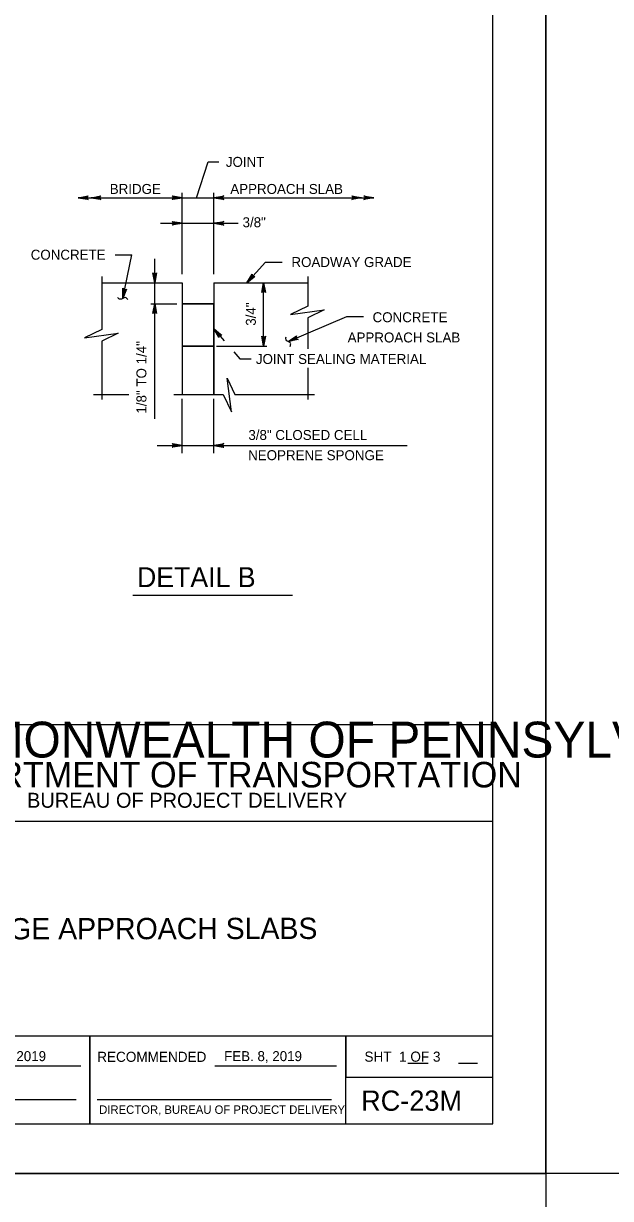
# Model space of a CAD drawing. Extents: x 638079 to 640019, y 297691 to 298879.
# Drawn here: x 638957.8 to 639134.4, y 298277.7 to 298631.2 of the extents above; entities that cross this region are included whole.
import ezdxf

# ---------------------------------------------------------------- set-up
doc = ezdxf.new("R2010")
doc.units = 0
doc.layers.add('1', color=7, linetype='Continuous')
doc.layers.add('PLT-BNDY', color=7, linetype='Continuous')

msp = doc.modelspace()

# ---------------------------------------------------------------- linework, layer by layer
at = {"layer": '1'}
for p, q in [((639009.91, 298578.75), (639013.4, 298589.57)), ((639013.4, 298589.57), (639016.61, 298589.57)), ((638974.31, 298578.75), (639063.24, 298578.75)), ((639005.54, 298555.74), (639005.54, 298580.25)), ((639015.08, 298555.74), (639015.08, 298580.25)), ((638999, 298571.05), (639022.46, 298571.05)), ((638985.41, 298561.59), (638990.41, 298561.59)), ((638987.7, 298548.47), (638990.41, 298561.59)), ((638997.32, 298512.27), (638997.32, 298560.41)), ((639025.06, 298553.2), (639030.61, 298559.39)), ((639030.61, 298559.39), (639035.62, 298559.39)), ((638981.39, 298555.01), (638981.39, 298539.15)), ((639043.36, 298555.01), (639043.36, 298546.18)), ((638981.39, 298553.2), (639005.54, 298553.2)), ((639005.54, 298553.2), (639005.54, 298519.53)), ((639005.54, 298553.2), (639005.54, 298546.86)), ((639015.08, 298553.2), (639015.08, 298546.86)), ((639015.08, 298553.2), (639043.36, 298553.2)), ((639030.05, 298534.15), (639030.05, 298553.2)), ((638996.14, 298546.86), (639003.95, 298546.86)), ((639005.54, 298546.86), (639005.54, 298534.15)), ((639005.54, 298546.86), (639015.08, 298546.86)), ((639015.08, 298546.86), (639015.08, 298519.53)), ((639037.49, 298535.48), (639055.14, 298543.04)), ((639043.36, 298542.66), (639043.36, 298533.34)), ((639055.14, 298543.04), (639060.14, 298543.04)), ((639015.08, 298539.31), (639018.19, 298535.72)), ((638981.39, 298535.63), (638981.39, 298518.07)), ((639005.54, 298534.15), (639015.08, 298534.15)), ((639015.92, 298534.15), (639031.05, 298534.15)), ((639021.13, 298532.35), (639022.95, 298530.26)), ((639022.95, 298530.26), (639026.35, 298530.26)), ((639043.36, 298527.58), (639043.36, 298518.07)), ((638978.87, 298519.53), (638989.49, 298519.53)), ((639003.06, 298519.53), (639017.92, 298519.53)), ((639021.44, 298519.53), (639045.41, 298519.53)), ((639005.54, 298501.96), (639005.54, 298518.27)), ((639015.08, 298501.96), (639015.08, 298518.27)), ((638998, 298504.24), (639073.25, 298504.24)), ((638990.71, 298459.2), (639038.76, 298459.2)), ((638938.35, 298317.61), (638975.04, 298317.61)), ((639015.35, 298317.61), (639052.04, 298317.61)), ((639073.45, 298318.41), (639079.6, 298318.41)), ((639088.71, 298318.41), (639094.45, 298318.41)), ((638901.43, 298307.53), (638973.67, 298307.53)), ((638979.96, 298307.53), (639050.52, 298307.53)), ((639115.03, 298285.23), (639115.03, 298285.23))]:
    msp.add_line(p, q, dxfattribs=at)
for points in [[(639099.03, 298300.23), (639099.03, 298864.23), (638313.03, 298864.23), (638313.03, 298300.23), (639099.03, 298300.23), (639099.03, 298326.59), (638899.03, 298326.59), (638899.03, 298391.26), (639099.03, 298391.26), (639099.03, 298420.23), (638899.03, 298420.23), (638899.03, 298300.23), (638977.83, 298300.23), (638977.83, 298326.59), (638977.83, 298300.23), (639054.83, 298300.23), (639054.83, 298326.59), (639054.83, 298314.27), (639099.03, 298314.27)], [(638974.31, 298578.75), (638977.29, 298579.31), (638977.06, 298579.15), (638976.94, 298578.95), (638976.91, 298578.75), (638976.94, 298578.55), (638977.06, 298578.35), (638977.29, 298578.19), (638974.31, 298578.75), (638977.06, 298578.35), (638976.94, 298578.55), (638974.31, 298578.75), (638976.91, 298578.75), (638976.94, 298578.95), (638974.31, 298578.75), (638977.06, 298579.15)], [(638978.14, 298578.75), (638981.12, 298579.31), (638980.89, 298579.15), (638980.77, 298578.95), (638980.74, 298578.75), (638980.77, 298578.55), (638980.89, 298578.35), (638981.12, 298578.19), (638978.14, 298578.75), (638980.89, 298578.35), (638980.77, 298578.55), (638978.14, 298578.75), (638980.74, 298578.75), (638980.77, 298578.95), (638978.14, 298578.75), (638980.89, 298579.15)], [(639005.54, 298578.75), (639002.56, 298578.19), (639002.67, 298578.27), (639002.79, 298578.35), (639002.85, 298578.45), (639002.91, 298578.55), (639002.92, 298578.65), (639002.94, 298578.75), (639002.92, 298578.85), (639002.91, 298578.95), (639002.85, 298579.05), (639002.79, 298579.15), (639002.67, 298579.23), (639002.56, 298579.31), (639005.54, 298578.75), (639002.67, 298579.23), (639002.79, 298579.15), (639005.54, 298578.75), (639002.85, 298579.05), (639002.91, 298578.95), (639005.54, 298578.75), (639002.92, 298578.85), (639002.94, 298578.75), (639005.54, 298578.75), (639002.92, 298578.65), (639002.91, 298578.55), (639005.54, 298578.75), (639002.85, 298578.45), (639002.79, 298578.35), (639005.54, 298578.75), (639002.67, 298578.27)], [(639015.08, 298578.75), (639018.06, 298579.31), (639017.95, 298579.23), (639017.83, 298579.15), (639017.77, 298579.05), (639017.71, 298578.95), (639017.7, 298578.85), (639017.68, 298578.75), (639017.7, 298578.65), (639017.71, 298578.55), (639017.77, 298578.45), (639017.83, 298578.35), (639017.95, 298578.27), (639018.06, 298578.19), (639015.08, 298578.75), (639017.95, 298578.27), (639017.83, 298578.35), (639015.08, 298578.75), (639017.77, 298578.45), (639017.71, 298578.55), (639015.08, 298578.75), (639017.7, 298578.65), (639017.68, 298578.75), (639015.08, 298578.75), (639017.7, 298578.85), (639017.71, 298578.95), (639015.08, 298578.75), (639017.77, 298579.05), (639017.83, 298579.15), (639015.08, 298578.75), (639017.95, 298579.23)], [(639059.57, 298578.75), (639056.58, 298578.19), (639056.81, 298578.35), (639056.93, 298578.55), (639056.97, 298578.75), (639056.93, 298578.95), (639056.81, 298579.15), (639056.58, 298579.31), (639059.57, 298578.75), (639056.81, 298579.15), (639056.93, 298578.95), (639059.57, 298578.75), (639056.97, 298578.75), (639056.93, 298578.55), (639059.57, 298578.75), (639056.81, 298578.35)], [(639063.24, 298578.75), (639060.25, 298578.19), (639060.48, 298578.35), (639060.6, 298578.55), (639060.64, 298578.75), (639060.6, 298578.95), (639060.48, 298579.15), (639060.25, 298579.31), (639063.24, 298578.75), (639060.48, 298579.15), (639060.6, 298578.95), (639063.24, 298578.75), (639060.64, 298578.75), (639060.6, 298578.55), (639063.24, 298578.75), (639060.48, 298578.35)], [(639005.54, 298571.05), (639002.56, 298570.49), (639002.67, 298570.57), (639002.79, 298570.65), (639002.85, 298570.75), (639002.91, 298570.85), (639002.92, 298570.95), (639002.94, 298571.05), (639002.92, 298571.15), (639002.91, 298571.25), (639002.85, 298571.35), (639002.79, 298571.45), (639002.67, 298571.53), (639002.56, 298571.61), (639005.54, 298571.05), (639002.67, 298571.53), (639002.79, 298571.45), (639005.54, 298571.05), (639002.85, 298571.35), (639002.91, 298571.25), (639005.54, 298571.05), (639002.92, 298571.15), (639002.94, 298571.05), (639005.54, 298571.05), (639002.92, 298570.95), (639002.91, 298570.85), (639005.54, 298571.05), (639002.85, 298570.75), (639002.79, 298570.65), (639005.54, 298571.05), (639002.67, 298570.57)], [(639015.08, 298571.05), (639018.06, 298571.61), (639017.95, 298571.53), (639017.83, 298571.45), (639017.77, 298571.35), (639017.71, 298571.25), (639017.7, 298571.15), (639017.68, 298571.05), (639017.7, 298570.95), (639017.71, 298570.85), (639017.77, 298570.75), (639017.83, 298570.65), (639017.95, 298570.57), (639018.06, 298570.49), (639015.08, 298571.05), (639017.95, 298570.57), (639017.83, 298570.65), (639015.08, 298571.05), (639017.77, 298570.75), (639017.71, 298570.85), (639015.08, 298571.05), (639017.7, 298570.95), (639017.68, 298571.05), (639015.08, 298571.05), (639017.7, 298571.15), (639017.71, 298571.25), (639015.08, 298571.05), (639017.77, 298571.35), (639017.83, 298571.45), (639015.08, 298571.05), (639017.95, 298571.53)], [(638997.32, 298553.2), (638996.76, 298556.18), (638996.92, 298555.95), (638997.12, 298555.83), (638997.32, 298555.8), (638997.52, 298555.83), (638997.72, 298555.95), (638997.88, 298556.18), (638997.32, 298553.2), (638997.72, 298555.95), (638997.52, 298555.83), (638997.32, 298553.2), (638997.32, 298555.8), (638997.12, 298555.83), (638997.32, 298553.2), (638996.92, 298555.95)], [(639025.06, 298553.2), (639026.64, 298555.79), (639026.6, 298555.51), (639026.67, 298555.29), (639026.8, 298555.13), (639026.97, 298555.03), (639027.2, 298554.98), (639027.47, 298555.05), (639025.06, 298553.2), (639027.2, 298554.98), (639026.97, 298555.03), (639025.06, 298553.2), (639026.8, 298555.13), (639026.67, 298555.29), (639025.06, 298553.2), (639026.6, 298555.51)], [(638987.7, 298548.47), (638987.76, 298551.51), (638987.87, 298551.25), (638988.04, 298551.09), (638988.23, 298551.02), (638988.43, 298551.01), (638988.65, 298551.09), (638988.85, 298551.28), (638987.7, 298548.47), (638988.65, 298551.09), (638988.43, 298551.01), (638987.7, 298548.47), (638988.23, 298551.02), (638988.04, 298551.09), (638987.7, 298548.47), (638987.87, 298551.25)], [(639030.05, 298553.2), (639030.61, 298550.22), (639030.45, 298550.45), (639030.25, 298550.56), (639030.05, 298550.6), (639029.85, 298550.56), (639029.65, 298550.45), (639029.49, 298550.22), (639030.05, 298553.2), (639029.65, 298550.45), (639029.85, 298550.56), (639030.05, 298553.2), (639030.05, 298550.6), (639030.25, 298550.56), (639030.05, 298553.2), (639030.45, 298550.45)], [(638997.32, 298546.86), (638997.88, 298543.88), (638997.72, 298544.11), (638997.52, 298544.22), (638997.32, 298544.26), (638997.12, 298544.22), (638996.92, 298544.11), (638996.76, 298543.88), (638997.32, 298546.86), (638996.92, 298544.11), (638997.12, 298544.22), (638997.32, 298546.86), (638997.32, 298544.26), (638997.52, 298544.22), (638997.32, 298546.86), (638997.72, 298544.11)], [(639043.36, 298546.18), (639038.17, 298543.65), (639048.32, 298545.03), (639043.36, 298542.66)], [(638981.39, 298539.15), (638976.21, 298536.61), (638986.36, 298537.99), (638981.39, 298535.63)], [(639015.08, 298539.31), (639017.46, 298537.42), (639017.32, 298537.46), (639017.19, 298537.49), (639017.07, 298537.47), (639016.96, 298537.45), (639016.87, 298537.4), (639016.79, 298537.34), (639016.72, 298537.27), (639016.66, 298537.19), (639016.62, 298537.08), (639016.58, 298536.97), (639016.6, 298536.83), (639016.61, 298536.69), (639015.08, 298539.31), (639016.6, 298536.83), (639016.58, 298536.97), (639015.08, 298539.31), (639016.62, 298537.08), (639016.66, 298537.19), (639015.08, 298539.31), (639016.72, 298537.27), (639016.79, 298537.34), (639015.08, 298539.31), (639016.87, 298537.4), (639016.96, 298537.45), (639015.08, 298539.31), (639017.07, 298537.47), (639017.19, 298537.49), (639015.08, 298539.31), (639017.32, 298537.46)], [(639030.05, 298534.15), (639029.49, 298537.13), (639029.65, 298536.9), (639029.85, 298536.78), (639030.05, 298536.75), (639030.25, 298536.78), (639030.45, 298536.9), (639030.61, 298537.13), (639030.05, 298534.15), (639030.45, 298536.9), (639030.25, 298536.78), (639030.05, 298534.15), (639030.05, 298536.75), (639029.85, 298536.78), (639030.05, 298534.15), (639029.65, 298536.9)], [(639037.49, 298535.48), (639040.01, 298537.17), (639039.86, 298536.93), (639039.83, 298536.7), (639039.88, 298536.51), (639039.99, 298536.34), (639040.18, 298536.2), (639040.45, 298536.14), (639037.49, 298535.48), (639040.18, 298536.2), (639039.99, 298536.34), (639037.49, 298535.48), (639039.88, 298536.51), (639039.83, 298536.7), (639037.49, 298535.48), (639039.86, 298536.93)], [(639017.92, 298519.53), (639020.45, 298514.34), (639019.07, 298524.49), (639021.44, 298519.53)], [(639005.54, 298504.24), (639002.56, 298503.68), (639002.67, 298503.76), (639002.79, 298503.84), (639002.85, 298503.94), (639002.91, 298504.04), (639002.92, 298504.14), (639002.94, 298504.24), (639002.92, 298504.34), (639002.91, 298504.44), (639002.85, 298504.54), (639002.79, 298504.64), (639002.67, 298504.72), (639002.56, 298504.8), (639005.54, 298504.24), (639002.67, 298504.72), (639002.79, 298504.64), (639005.54, 298504.24), (639002.85, 298504.54), (639002.91, 298504.44), (639005.54, 298504.24), (639002.92, 298504.34), (639002.94, 298504.24), (639005.54, 298504.24), (639002.92, 298504.14), (639002.91, 298504.04), (639005.54, 298504.24), (639002.85, 298503.94), (639002.79, 298503.84), (639005.54, 298504.24), (639002.67, 298503.76)], [(639015.08, 298504.24), (639018.06, 298504.8), (639017.95, 298504.72), (639017.83, 298504.64), (639017.77, 298504.54), (639017.71, 298504.44), (639017.7, 298504.34), (639017.68, 298504.24), (639017.7, 298504.14), (639017.71, 298504.04), (639017.77, 298503.94), (639017.83, 298503.84), (639017.95, 298503.76), (639018.06, 298503.68), (639015.08, 298504.24), (639017.95, 298503.76), (639017.83, 298503.84), (639015.08, 298504.24), (639017.77, 298503.94), (639017.71, 298504.04), (639015.08, 298504.24), (639017.7, 298504.14), (639017.68, 298504.24), (639015.08, 298504.24), (639017.7, 298504.34), (639017.71, 298504.44), (639015.08, 298504.24), (639017.77, 298504.54), (639017.83, 298504.64), (639015.08, 298504.24), (639017.95, 298504.72)]]:
    msp.add_lwpolyline(points, dxfattribs=at)
for points in [[(639005.54, 298534.15), (639015.08, 298534.15), (639015.08, 298546.86), (639005.54, 298546.86)], [(639005.54, 298519.53), (639015.08, 298519.53), (639015.08, 298534.15), (639005.54, 298534.15)]]:
    msp.add_lwpolyline(points, close=True, dxfattribs=at)
for points in [[(638989.22, 298548.13), (638988.47, 298548.75), (638986.93, 298548.19), (638986.18, 298548.77)], [(639038.07, 298534.04), (639038.16, 298535.01), (639036.81, 298535.96), (639036.86, 298536.9)]]:
    msp.add_spline(points, degree=3, dxfattribs=at)
at = {"layer": 'PLT-BNDY'}
for points in [[(638274.03, 298879.23), (639115.03, 298879.23), (639115.03, 298285.23), (638274.03, 298285.23)], [(639115.03, 298879.23), (639956.03, 298879.23), (639956.03, 298285.23), (639115.03, 298285.23)], [(638274.03, 298285.23), (639115.03, 298285.23), (639115.03, 297691.23), (638274.03, 297691.23)]]:
    msp.add_lwpolyline(points, close=True, dxfattribs=at)

# ---------------------------------------------------------------- texts
at = {"layer": '1'}
for s, height, p in [('JOINT', 3, (639018.71, 298588.03)), ('BRIDGE', 3, (638983.78, 298579.89)), ('APPROACH SLAB', 3, (639020.05, 298579.89)), ('3/8"', 3, (639023.74, 298569.87)), ('CONCRETE', 3, (638960.01, 298560.11)), ('ROADWAY GRADE', 3, (639038.45, 298557.9)), ('CONCRETE', 3, (639062.86, 298541.3)), ('APPROACH SLAB', 3, (639055.35, 298535.22)), ('JOINT SEALING MATERIAL', 3, (639027.75, 298528.74)), ('3/8" CLOSED CELL', 3, (639025.49, 298505.89)), ('NEOPRENE SPONGE', 3, (639025.42, 298499.81)), ('DETAIL B', 6, (638991.99, 298461.62)), ('COMMONWEALTH OF PENNSYLVANIA', 10.7834, (638912.18, 298410.37)), ('DEPARTMENT OF TRANSPORTATION', 7.6843, (638922.25, 298401.38)), ('BUREAU OF PROJECT DELIVERY', 4.5, (638958.89, 298395.26)), ('FEB. 8, 2019', 3, (638941.2, 298319.05)), ('RECOMMENDED', 3.048, (638980.01, 298318.82)), ('FEB. 8, 2019', 3, (639018.2, 298319.05)), ('SHT  1 OF 3', 3.048, (639060.41, 298318.87)), ('RC-23M', 6.096, (639059.42, 298304.11)), ('DIRECTOR, BUREAU OF PROJECT DELIVERY', 2.54, (638980.6, 298303.19))]:
    msp.add_text(s, height=height, dxfattribs=at).set_placement(p)
for s, height, rotation, p in [('3/4"', 3, 90, (639027.73, 298540.25)), ('1/8" TO 1/4"', 3, 90, (638994.81, 298513.82)), ('BRIDGE APPROACH SLABS', 6.4, 0.0819, (638933.07, 298355.63))]:
    msp.add_text(s, height=height, rotation=rotation, dxfattribs=at).set_placement(p)

doc.saveas('drawing.dxf')
